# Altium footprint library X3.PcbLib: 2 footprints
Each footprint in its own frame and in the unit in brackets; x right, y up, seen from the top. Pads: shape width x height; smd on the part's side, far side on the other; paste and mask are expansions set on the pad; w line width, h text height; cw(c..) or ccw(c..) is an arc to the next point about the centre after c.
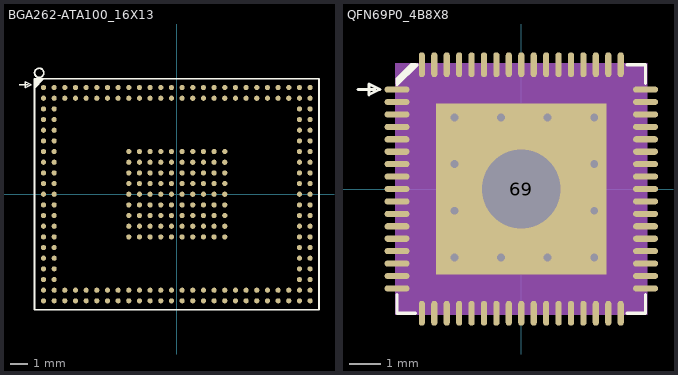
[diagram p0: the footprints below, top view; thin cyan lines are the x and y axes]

## BGA262-ATA100_16X13 [mm] "BGA262-ATA100_16X13"
pads (262):
  round 0.29 smd: A1(-7.5,6) A2(-6.9,6) A3(-6.3,6) A4(-5.7,6) A5(-5.1,6) A6(-4.5,6) A7(-3.9,6) A8(-3.3,6) A9(-2.7,6) A10(-2.1,6) A11(-1.5,6) A12(-0.9,6) A13(-0.3,6) A14(0.3,6) A15(0.9,6) A16(1.5,6) A17(2.1,6) A18(2.7,6) A19(3.3,6) A20(3.9,6) A21(4.5,6) A22(5.1,6) A23(5.7,6) A24(6.3,6) A25(6.9,6) A26(7.5,6) B1(-7.5,5.4) B2(-6.9,5.4) B3(-6.3,5.4) B4(-5.7,5.4) B5(-5.1,5.4) B6(-4.5,5.4) B7(-3.9,5.4) B8(-3.3,5.4) B9(-2.7,5.4) B10(-2.1,5.4) B11(-1.5,5.4) B12(-0.9,5.4) B13(-0.3,5.4) B14(0.3,5.4) B15(0.9,5.4) B16(1.5,5.4) B17(2.1,5.4) B18(2.7,5.4) B19(3.3,5.4) B20(3.9,5.4) B21(4.5,5.4) B22(5.1,5.4) B23(5.7,5.4) B24(6.3,5.4) B25(6.9,5.4) B26(7.5,5.4) C1(-7.5,4.8) C2(-6.9,4.8) C25(6.9,4.8) C26(7.5,4.8) D1(-7.5,4.2) D2(-6.9,4.2) D25(6.9,4.2) D26(7.5,4.2) E1(-7.5,3.6) E2(-6.9,3.6) E25(6.9,3.6) E26(7.5,3.6) F1(-7.5,3) F2(-6.9,3) F25(6.9,3) F26(7.5,3) G1(-7.5,2.4) G2(-6.9,2.4) G9(-2.7,2.4) G10(-2.1,2.4) G11(-1.5,2.4) G12(-0.9,2.4) G13(-0.3,2.4) G14(0.3,2.4) G15(0.9,2.4) G16(1.5,2.4) G17(2.1,2.4) G18(2.7,2.4) G25(6.9,2.4) G26(7.5,2.4) H1(-7.5,1.8) H2(-6.9,1.8) H9(-2.7,1.8) H10(-2.1,1.8) H11(-1.5,1.8) H12(-0.9,1.8) H13(-0.3,1.8) H14(0.3,1.8) H15(0.9,1.8) H16(1.5,1.8) H17(2.1,1.8) H18(2.7,1.8) H25(6.9,1.8) H26(7.5,1.8) J1(-7.5,1.2) J2(-6.9,1.2) J9(-2.7,1.2) J10(-2.1,1.2) J11(-1.5,1.2) J12(-0.9,1.2) J13(-0.3,1.2) J14(0.3,1.2) J15(0.9,1.2) J16(1.5,1.2) J17(2.1,1.2) J18(2.7,1.2) J25(6.9,1.2) J26(7.5,1.2) K1(-7.5,0.6) K2(-6.9,0.6) K9(-2.7,0.6) K10(-2.1,0.6) K11(-1.5,0.6) K12(-0.9,0.6) K13(-0.3,0.6) K14(0.3,0.6) K15(0.9,0.6) K16(1.5,0.6) K17(2.1,0.6) K18(2.7,0.6) K25(6.9,0.6) K26(7.5,0.6) L1(-7.5,0) L2(-6.9,0) L9(-2.7,0) L10(-2.1,0) L11(-1.5,0) L12(-0.9,0) L13(-0.3,0) L14(0.3,0) L15(0.9,0) L16(1.5,0) L17(2.1,0) L18(2.7,0) L25(6.9,0) L26(7.5,0) M1(-7.5,-0.6) M2(-6.9,-0.6) M9(-2.7,-0.6) M10(-2.1,-0.6) M11(-1.5,-0.6) M12(-0.9,-0.6) M13(-0.3,-0.6) M14(0.3,-0.6) M15(0.9,-0.6) M16(1.5,-0.6) M17(2.1,-0.6) M18(2.7,-0.6) M25(6.9,-0.6) M26(7.5,-0.6) N1(-7.5,-1.2) N2(-6.9,-1.2) N9(-2.7,-1.2) N10(-2.1,-1.2) N11(-1.5,-1.2) N12(-0.9,-1.2) N13(-0.3,-1.2) N14(0.3,-1.2) N15(0.9,-1.2) N16(1.5,-1.2) N17(2.1,-1.2) N18(2.7,-1.2) N25(6.9,-1.2) N26(7.5,-1.2) P1(-7.5,-1.8) P2(-6.9,-1.8) P9(-2.7,-1.8) P10(-2.1,-1.8) P11(-1.5,-1.8) P12(-0.9,-1.8) P13(-0.3,-1.8) P14(0.3,-1.8) P15(0.9,-1.8) P16(1.5,-1.8) P17(2.1,-1.8) P18(2.7,-1.8) P25(6.9,-1.8) P26(7.5,-1.8) R1(-7.5,-2.4) R2(-6.9,-2.4) R9(-2.7,-2.4) R10(-2.1,-2.4) R11(-1.5,-2.4) R12(-0.9,-2.4) R13(-0.3,-2.4) R14(0.3,-2.4) R15(0.9,-2.4) R16(1.5,-2.4) R17(2.1,-2.4) R18(2.7,-2.4) R25(6.9,-2.4) R26(7.5,-2.4) T1(-7.5,-3) T2(-6.9,-3) T25(6.9,-3) T26(7.5,-3) U1(-7.5,-3.6) U2(-6.9,-3.6) U25(6.9,-3.6) U26(7.5,-3.6) V1(-7.5,-4.2) V2(-6.9,-4.2) V25(6.9,-4.2) V26(7.5,-4.2) W1(-7.5,-4.8) W2(-6.9,-4.8) W25(6.9,-4.8) W26(7.5,-4.8) X1(-7.5,-5.4) X2(-6.9,-5.4) X3(-6.3,-5.4) X4(-5.7,-5.4) X5(-5.1,-5.4) X6(-4.5,-5.4) X7(-3.9,-5.4) X8(-3.3,-5.4) X9(-2.7,-5.4) X10(-2.1,-5.4) X11(-1.5,-5.4) X12(-0.9,-5.4) X13(-0.3,-5.4) X14(0.3,-5.4) X15(0.9,-5.4) X16(1.5,-5.4) X17(2.1,-5.4) X18(2.7,-5.4) X19(3.3,-5.4) X20(3.9,-5.4) X21(4.5,-5.4) X22(5.1,-5.4) X23(5.7,-5.4) X24(6.3,-5.4) X25(6.9,-5.4) X26(7.5,-5.4) Y1(-7.5,-6) Y2(-6.9,-6) Y3(-6.3,-6) Y4(-5.7,-6) Y5(-5.1,-6) Y6(-4.5,-6) Y7(-3.9,-6) Y8(-3.3,-6) Y9(-2.7,-6) Y10(-2.1,-6) Y11(-1.5,-6) Y12(-0.9,-6) Y13(-0.3,-6) Y14(0.3,-6) Y15(0.9,-6) Y16(1.5,-6) Y17(2.1,-6) Y18(2.7,-6) Y19(3.3,-6) Y20(3.9,-6) Y21(4.5,-6) Y22(5.1,-6) Y23(5.7,-6) Y24(6.3,-6) Y25(6.9,-6) Y26(7.5,-6)
Top Overlay:
  circle w0.1: c-7.74,6.825 r0.26
  lines w0.08: -8.878,6.164 -8.353,6.164 ; -8.528,5.989 -8.528,6.339 -8.178,6.164 -8.528,5.989
  lines w0.1: -8,6.4 -7.9,6.5 -7.8,6.5 -8,6.3 -8,6.2 -7.7,6.5 -7.6,6.5 -8,6.1 -8,6 -7.5,6.5 ; -8,-6.5 8,-6.5 8,6.5 -8,6.5 -8,-6.5

## QFN69P0_4B8X8 [mm] "QFN69P0_4B8X8"
pads (69):
  oval 0.8x0.2 smd: 1(-4,3.2) 2(-4,2.8) 3(-4,2.4) 4(-4,2) 5(-4,1.6) 6(-4,1.2) 7(-4,0.8) 8(-4,0.4) 9(-4,0) 10(-4,-0.4) 11(-4,-0.8) 12(-4,-1.2) 13(-4,-1.6) 14(-4,-2) 15(-4,-2.4) 16(-4,-2.8) 17(-4,-3.2) 35(4,-3.2) 36(4,-2.8) 37(4,-2.4) 38(4,-2) 39(4,-1.6) 40(4,-1.2) 41(4,-0.8) 42(4,-0.4) 43(4,0) 44(4,0.4) 45(4,0.8) 46(4,1.2) 47(4,1.6) 48(4,2) 49(4,2.4) 50(4,2.8) 51(4,3.2)
  oval 0.2x0.8 smd: 18(-3.2,-4) 19(-2.8,-4) 20(-2.4,-4) 21(-2,-4) 22(-1.6,-4) 23(-1.2,-4) 24(-0.8,-4) 25(-0.4,-4) 26(0,-4) 27(0.4,-4) 28(0.8,-4) 29(1.2,-4) 30(1.6,-4) 31(2,-4) 32(2.4,-4) 33(2.8,-4) 34(3.2,-4) 52(3.2,4) 53(2.8,4) 54(2.4,4) 55(2,4) 56(1.6,4) 57(1.2,4) 58(0.8,4) 59(0.4,4) 60(0,4) 61(-0.4,4) 62(-0.8,4) 63(-1.2,4) 64(-1.6,4) 65(-2,4) 66(-2.4,4) 67(-2.8,4) 68(-3.2,4)
  rect 5.5x5.5 / inner rect 3.6x3.6 / far side rect 5.5x5.5 hole 2.54: 69(0,0)
via 2.35,-2.2 diameter 0.457 hole 0.254
via 0.85,-2.2 diameter 0.457 hole 0.254
via -0.65,-2.2 diameter 0.457 hole 0.254
via -2.15,-2.2 diameter 0.457 hole 0.254
via 2.35,-0.7 diameter 0.457 hole 0.254
via -2.15,-0.7 diameter 0.457 hole 0.254
via 2.35,0.8 diameter 0.457 hole 0.254
via -2.15,0.8 diameter 0.457 hole 0.254
via 2.35,2.3 diameter 0.457 hole 0.254
via 0.85,2.3 diameter 0.457 hole 0.254
via -0.65,2.3 diameter 0.457 hole 0.254
via -2.15,2.3 diameter 0.457 hole 0.254
Top Overlay:
  lines w0.1: -5.255,3.208 -4.73,3.208 ; -4,-3.4 -4,-4 -3.4,-4 ; -4,3.35 -3.35,4 ; -4,3.4 -4,3.55 ; -4,3.45 -3.45,4 ; -3.4,4 -3.55,4 ; 3.4,-4 4,-4 4,-3.4 ; 3.4,4 4,4 4,3.4 ; -4,3.55 -3.55,4 ; -4,3.55 -3.55,4 ; -4.905,3.033 -4.555,3.208 -4.905,3.383 -4.905,3.033
Mechanical 16:
  pour cut-out: -4.05,-4.05 4.05,-4.05 4.05,4.05 -4.05,4.05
